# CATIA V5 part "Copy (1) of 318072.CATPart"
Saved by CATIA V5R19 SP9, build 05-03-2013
Part number: Copy (1) of 318072
Source: Unknown
Bounding box of the stored display mesh (mm): x -164.771 to -4.52, y -231.182 to -196.661, z 470.762 to 488.942
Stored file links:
  D:\16-SIL\kale oto\R19_V2\Copy (1) of 318072.CATPart
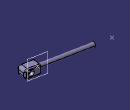
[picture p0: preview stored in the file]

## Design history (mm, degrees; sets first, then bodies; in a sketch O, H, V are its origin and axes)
Set1
  Point1 to Point3: stored without definition
  Plane1: type OffsetPt, RefPlane face of Solid1, RefPoint Point3
Body1 "241\\233\\232\\MANIFOLD_SOLID_BREP #159996" (main body)
  Solid1: solid without history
